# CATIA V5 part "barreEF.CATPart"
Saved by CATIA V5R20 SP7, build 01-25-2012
Part number: barreEF
Publications: "pivot_EF_CE", "pivot_EF_FG", "Plan_Ref"
Bounding box of the stored display mesh (mm): x 15 to 23, y 1.144 to 203.205, z 140.824 to 294.494
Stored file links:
  G:\IAO\apres\barreEF.CATPart
  G:\IAO\apres\psedsuay.CATProduct
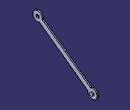
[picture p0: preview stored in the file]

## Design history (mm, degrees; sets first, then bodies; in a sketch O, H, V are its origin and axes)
External parameters (linked from other documents)
  External.Longueur_AB = 100 mm
  External.Largeur = 15 mm
  External.Diametre = 30 mm
  External.Epaisseur = 4 mm
  External.Diametre_pivot = 10 mm
Set1
  Point1 "Point_E": linked copy from another document
  Point2 "Point_F": linked copy from another document
  Plane1 "Plan_Ref": linked copy from another document
Set2 "skelette"
  Line1 "Barre_EF": type PtPt, FirstPoint Point1, SecondPoint Point2
  Line2 "pivot_EF_CE": type Normal, RefPoint Point1, RefSkin Plane1, Start -20, End 20
  Line3 "pivot_EF_FG": type Normal, RefPoint Point2, RefSkin Plane1, Start -20, End 20
Set3 "piece"
  Plane2: type OffsetPt, RefPlane yz-plane, RefPoint Point2
  Plane3: type Offset, RefPlane Plane2, Offset 15 {= 0.15*External.Longueur_AB}
  Sketch1 on Plane3, origin (15, 0, 0), H (0, 1, 0), V (0, 0, 1)
    arc A1 centre (188.2401, 155.7819) radius 15 from (173.3147, 157.2755) to (182.0709, 169.4545) ccw
    arc A2 centre (16.1097, 279.5362) radius 15 from (31.0352, 278.0426) to (22.279, 265.8636) ccw
    construction line L1 (188.2401, 155.7819) -> (16.1097, 279.5362)
    line L2 (173.3147, 157.2755) -> (22.279, 265.8636)
    line L3 (31.0352, 278.0426) -> (182.0709, 169.4545)
    reference projected point E1 (188.2401, 155.7819) from Line2
    reference projected point E2 (16.1097, 279.5362) from Line3
    radius A2 = 15 {= External.Diametre /2}
    radius A1 = 15 {= External.Diametre /2}
    distance L3 L2 = 15 {= External.Largeur}
    parallelism: L2 L1, L3 L1
    symmetry: L3 L2 L1
    concentricity: A1 E1, A2 E2
  Plane4: type Offset, RefPlane Plane3, Offset 4 {= External.Epaisseur}
  Sketch2 on Plane4, origin (19, 0, 0), H (0, 1, 0), V (0, 0, 1)
    circle A1 centre (188.2401, 155.7819) radius 5
    reference projected point E1 (188.2401, 155.7819) from Line2
    radius A1 = 5 {= External.Diametre_pivot /2}
    concentricity: A1 E1
Body1 (main body)
  Pad1: profile Sketch1, direction (1, 0, 0), length 4 {= External.Epaisseur}
  Pad2: profile Sketch2, direction (1, 0, 0), length 4 {= External.Epaisseur}
  Sketch3 on Plane4, origin (19, 16.1097, 279.5362), H (0, 1, 0), V (0, 0, 1)
    point P1 (0, 0)
    reference projected point E1 (0, 0) from Line3
    coincidence: P1 E1
  Hole1: placed by Sketch3, at (19, 16.1097, 279.5362) direction (-1, 0, 0), diameter 10 {= External.Diametre_pivot}, through (limit type 3)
